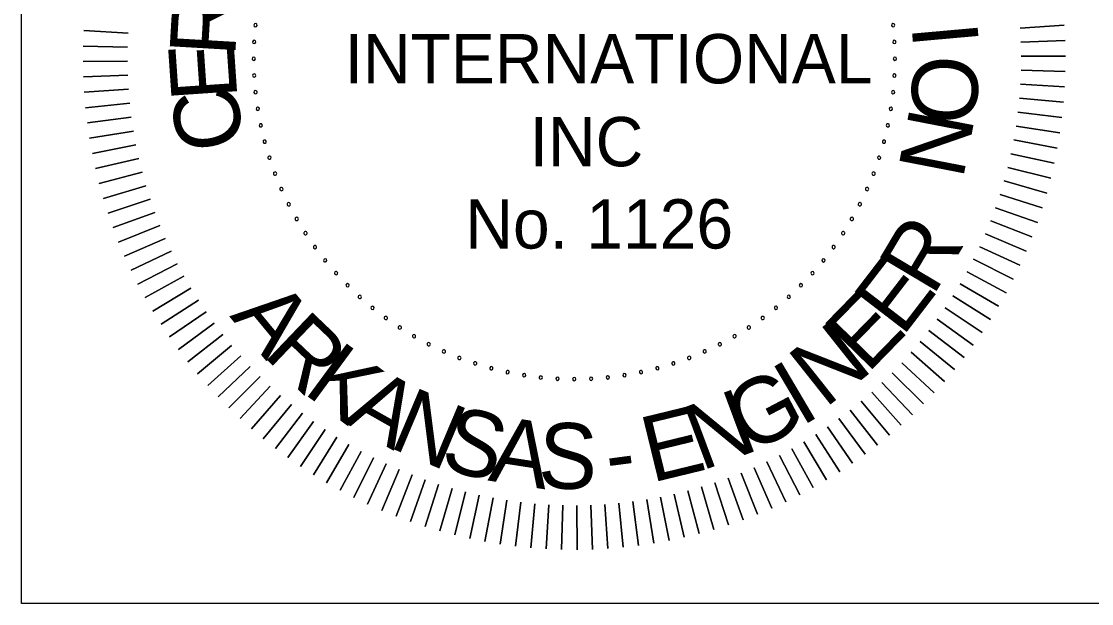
# Model space of a CAD drawing. Extents: x -984 to 3998, y 83 to 2143.
# Drawn here: x 2730.1 to 3001.2, y 212.7 to 360.3 of the extents above; entities that cross this region are included whole.
import ezdxf

# ---------------------------------------------------------------- set-up
doc = ezdxf.new("R2010")
doc.units = 0
doc.layers.add('Level 55', color=7, linetype='Continuous')
doc.layers.add('Level 57', color=7, linetype='Continuous')

msp = doc.modelspace()

# ---------------------------------------------------------------- linework, layer by layer
at = {"layer": 'Level 55'}
for points in [[(2757.15, 357.32), (2745.94, 357.97)], [(2745.94, 357.97), (2757.15, 357.32)], [(2994.33, 359.35), (2983.13, 358.58)], [(2983.13, 358.58), (2994.33, 359.35)], [(2994.54, 355.45), (2983.32, 355.03)], [(2983.32, 355.03), (2994.54, 355.45)], [(2757, 353.77), (2745.78, 354.06)], [(2745.78, 354.06), (2757, 353.77)], [(2756.96, 350.21), (2745.74, 350.15)], [(2745.74, 350.15), (2756.96, 350.21)], [(2994.62, 351.54), (2983.4, 351.48)], [(2983.4, 351.48), (2994.62, 351.54)], [(2994.58, 347.63), (2983.36, 347.92)], [(2983.36, 347.92), (2994.58, 347.63)], [(2757.04, 346.66), (2745.82, 346.24)], [(2745.82, 346.24), (2757.04, 346.66)], [(2994.42, 343.72), (2983.21, 344.37)], [(2983.21, 344.37), (2994.42, 343.72)], [(2757.23, 343.11), (2746.03, 342.34)], [(2746.03, 342.34), (2757.23, 343.11)], [(2757.53, 339.56), (2746.36, 338.44)], [(2746.36, 338.44), (2757.53, 339.56)], [(2994.13, 339.82), (2982.95, 340.82)], [(2982.95, 340.82), (2994.13, 339.82)], [(2993.73, 335.94), (2982.58, 337.28)], [(2982.58, 337.28), (2993.73, 335.94)], [(2757.94, 336.03), (2746.81, 334.56)], [(2746.81, 334.56), (2757.94, 336.03)], [(2993.2, 332.06), (2982.1, 333.76)], [(2982.1, 333.76), (2993.2, 332.06)], [(2758.46, 332.51), (2747.38, 330.69)], [(2747.38, 330.69), (2758.46, 332.51)], [(2759.09, 329.01), (2748.08, 326.85)], [(2748.08, 326.85), (2759.09, 329.01)], [(2992.55, 328.21), (2981.51, 330.25)], [(2981.51, 330.25), (2992.55, 328.21)], [(2759.83, 325.53), (2748.89, 323.02)], [(2748.89, 323.02), (2759.83, 325.53)], [(2991.77, 324.38), (2980.81, 326.76)], [(2980.81, 326.76), (2991.77, 324.38)], [(2990.88, 320.57), (2980, 323.3)], [(2980, 323.3), (2990.88, 320.57)], [(2760.68, 322.08), (2749.82, 319.23)], [(2749.82, 319.23), (2760.68, 322.08)], [(2761.64, 318.65), (2750.88, 315.46)], [(2750.88, 315.46), (2761.64, 318.65)], [(2989.87, 316.79), (2979.08, 319.86)], [(2979.08, 319.86), (2989.87, 316.79)], [(2762.7, 315.26), (2752.05, 311.73)], [(2752.05, 311.73), (2762.7, 315.26)], [(2988.74, 313.05), (2978.05, 316.46)], [(2978.05, 316.46), (2988.74, 313.05)], [(2763.87, 311.9), (2753.33, 308.04)], [(2753.33, 308.04), (2763.87, 311.9)], [(2987.5, 309.35), (2976.92, 313.09)], [(2976.92, 313.09), (2987.5, 309.35)], [(2986.14, 305.68), (2975.68, 309.75)], [(2975.68, 309.75), (2986.14, 305.68)], [(2765.15, 308.58), (2754.74, 304.39)], [(2754.74, 304.39), (2765.15, 308.58)], [(2984.66, 302.06), (2974.34, 306.46)], [(2974.34, 306.46), (2984.66, 302.06)], [(2766.53, 305.3), (2756.25, 300.79)], [(2756.25, 300.79), (2766.53, 305.3)], [(2768.01, 302.07), (2757.88, 297.23)], [(2757.88, 297.23), (2768.01, 302.07)], [(2983.07, 298.49), (2972.89, 303.21)], [(2972.89, 303.21), (2983.07, 298.49)], [(2769.59, 298.88), (2759.62, 293.73)], [(2759.62, 293.73), (2769.59, 298.88)], [(2981.37, 294.97), (2971.34, 300.01)], [(2971.34, 300.01), (2981.37, 294.97)], [(2771.27, 295.75), (2761.47, 290.29)], [(2761.47, 290.29), (2771.27, 295.75)], [(2979.56, 291.5), (2969.7, 296.86)], [(2969.7, 296.86), (2979.56, 291.5)], [(2977.64, 288.1), (2967.95, 293.76)], [(2967.95, 293.76), (2977.64, 288.1)], [(2773.05, 292.67), (2763.42, 286.9)], [(2763.42, 286.9), (2773.05, 292.67)], [(2975.62, 284.75), (2966.11, 290.71)], [(2966.11, 290.71), (2975.62, 284.75)], [(2774.93, 289.65), (2765.49, 283.58)], [(2765.49, 283.58), (2774.93, 289.65)], [(2973.49, 281.47), (2964.18, 287.73)], [(2964.18, 287.73), (2973.49, 281.47)], [(2776.9, 286.69), (2767.65, 280.33)], [(2767.65, 280.33), (2776.9, 286.69)], [(2971.26, 278.26), (2962.15, 284.81)], [(2962.15, 284.81), (2971.26, 278.26)], [(2778.96, 283.79), (2769.92, 277.14)], [(2769.92, 277.14), (2778.96, 283.79)], [(2781.11, 280.96), (2772.28, 274.03)], [(2772.28, 274.03), (2781.11, 280.96)], [(2968.93, 275.12), (2960.03, 281.95)], [(2960.03, 281.95), (2968.93, 275.12)], [(2783.35, 278.19), (2774.74, 270.99)], [(2774.74, 270.99), (2783.35, 278.19)], [(2966.51, 272.06), (2957.82, 279.16)], [(2957.82, 279.16), (2966.51, 272.06)], [(2785.67, 275.5), (2777.3, 268.03)], [(2777.3, 268.03), (2785.67, 275.5)], [(2963.98, 269.07), (2955.52, 276.45)], [(2955.52, 276.45), (2963.98, 269.07)], [(2788.08, 272.88), (2779.94, 265.16)], [(2779.94, 265.16), (2788.08, 272.88)], [(2958.66, 263.34), (2950.68, 271.23)], [(2950.68, 271.23), (2958.66, 263.34)], [(2961.37, 266.17), (2953.14, 273.8)], [(2953.14, 273.8), (2961.37, 266.17)], [(2790.57, 270.34), (2782.68, 262.36)], [(2782.68, 262.36), (2790.57, 270.34)], [(2955.87, 260.61), (2948.14, 268.75)], [(2948.14, 268.75), (2955.87, 260.61)], [(2793.14, 267.88), (2785.5, 259.66)], [(2785.5, 259.66), (2793.14, 267.88)], [(2952.99, 257.96), (2945.53, 266.34)], [(2945.53, 266.34), (2952.99, 257.96)], [(2788.41, 257.04), (2795.78, 265.5)], [(2795.78, 265.5), (2788.41, 257.04)], [(2791.39, 254.52), (2798.5, 263.21)], [(2798.5, 263.21), (2791.39, 254.52)], [(2950.04, 255.41), (2942.83, 264.01)], [(2942.83, 264.01), (2950.04, 255.41)], [(2794.46, 252.09), (2801.29, 261)], [(2801.29, 261), (2794.46, 252.09)], [(2947, 252.94), (2940.07, 261.77)], [(2940.07, 261.77), (2947, 252.94)], [(2797.6, 249.76), (2804.14, 258.88)], [(2804.14, 258.88), (2797.6, 249.76)], [(2943.89, 250.58), (2937.24, 259.62)], [(2937.24, 259.62), (2943.89, 250.58)], [(2800.81, 247.53), (2807.07, 256.85)], [(2807.07, 256.85), (2800.81, 247.53)], [(2804.09, 245.41), (2810.05, 254.92)], [(2810.05, 254.92), (2804.09, 245.41)], [(2937.44, 246.15), (2931.38, 255.59)], [(2931.38, 255.59), (2937.44, 246.15)], [(2940.7, 248.31), (2934.34, 257.56)], [(2934.34, 257.56), (2940.7, 248.31)], [(2807.43, 243.38), (2813.09, 253.07)], [(2813.09, 253.07), (2807.43, 243.38)], [(2934.12, 244.09), (2928.36, 253.72)], [(2928.36, 253.72), (2934.12, 244.09)], [(2810.84, 241.46), (2816.19, 251.33)], [(2816.19, 251.33), (2810.84, 241.46)], [(2814.3, 239.65), (2819.34, 249.68)], [(2819.34, 249.68), (2814.3, 239.65)], [(2927.29, 240.28), (2922.14, 250.25)], [(2922.14, 250.25), (2927.29, 240.28)], [(2930.74, 242.13), (2925.28, 251.94)], [(2925.28, 251.94), (2930.74, 242.13)], [(2817.82, 237.95), (2822.55, 248.13)], [(2822.55, 248.13), (2817.82, 237.95)], [(2920.24, 236.92), (2915.72, 247.19)], [(2915.72, 247.19), (2920.24, 236.92)], [(2923.79, 238.54), (2918.96, 248.67)], [(2918.96, 248.67), (2923.79, 238.54)], [(2821.4, 236.37), (2825.8, 246.69)], [(2825.8, 246.69), (2821.4, 236.37)], [(2825.02, 234.89), (2829.09, 245.35)], [(2829.09, 245.35), (2825.02, 234.89)], [(2828.68, 233.53), (2832.42, 244.11)], [(2832.42, 244.11), (2828.68, 233.53)], [(2912.99, 234), (2909.13, 244.54)], [(2909.13, 244.54), (2912.99, 234)], [(2916.63, 235.4), (2912.45, 245.81)], [(2912.45, 245.81), (2916.63, 235.4)], [(2832.39, 232.28), (2835.8, 242.97)], [(2835.8, 242.97), (2832.39, 232.28)], [(2836.13, 231.15), (2839.2, 241.95)], [(2839.2, 241.95), (2836.13, 231.15)], [(2901.8, 230.49), (2898.95, 241.34)], [(2898.95, 241.34), (2901.8, 230.49)], [(2905.56, 231.54), (2902.37, 242.3)], [(2902.37, 242.3), (2905.56, 231.54)], [(2909.29, 232.71), (2905.77, 243.36)], [(2905.77, 243.36), (2909.29, 232.71)], [(2839.91, 230.14), (2842.64, 241.03)], [(2842.64, 241.03), (2839.91, 230.14)], [(2843.71, 229.25), (2846.1, 240.22)], [(2846.1, 240.22), (2843.71, 229.25)], [(2847.54, 228.48), (2849.59, 239.52)], [(2849.59, 239.52), (2847.54, 228.48)], [(2851.4, 227.83), (2853.09, 238.92)], [(2853.09, 238.92), (2851.4, 227.83)], [(2890.33, 228.05), (2888.52, 239.12)], [(2888.52, 239.12), (2890.33, 228.05)], [(2894.18, 228.74), (2892.02, 239.75)], [(2892.02, 239.75), (2894.18, 228.74)], [(2898, 229.55), (2895.49, 240.49)], [(2895.49, 240.49), (2898, 229.55)], [(2855.27, 227.3), (2856.62, 238.44)], [(2856.62, 238.44), (2855.27, 227.3)], [(2859.16, 226.89), (2860.15, 238.07)], [(2860.15, 238.07), (2859.16, 226.89)], [(2863.06, 226.61), (2863.7, 237.81)], [(2863.7, 237.81), (2863.06, 226.61)], [(2866.97, 226.45), (2867.26, 237.66)], [(2867.26, 237.66), (2866.97, 226.45)], [(2870.87, 226.41), (2870.81, 237.63)], [(2870.81, 237.63), (2870.87, 226.41)], [(2874.78, 226.49), (2874.37, 237.7)], [(2874.37, 237.7), (2874.78, 226.49)], [(2878.69, 226.7), (2877.92, 237.89)], [(2877.92, 237.89), (2878.69, 226.7)], [(2882.58, 227.02), (2881.46, 238.19)], [(2881.46, 238.19), (2882.58, 227.02)], [(2886.47, 227.47), (2885, 238.6)], [(2885, 238.6), (2886.47, 227.47)]]:
    msp.add_lwpolyline(points, dxfattribs=at)
for centre, start, end in [((2789.41, 359.33), 84, 264), ((2789.41, 359.33), 264, 84), ((2950.95, 359.33), 96, 276), ((2950.95, 359.33), 276, 96), ((2789.08, 355.1), 87, 267), ((2789.08, 355.1), 267, 87), ((2951.28, 355.1), 93, 273), ((2951.28, 355.1), 273, 93), ((2788.97, 350.85), 90, 270), ((2788.97, 350.85), 270, 90), ((2951.4, 350.85), 90, 270), ((2951.4, 350.85), 270, 90), ((2789.08, 346.59), 93, 273), ((2789.08, 346.59), 273, 93), ((2951.28, 346.59), 87, 267), ((2951.28, 346.59), 267, 87), ((2789.41, 342.36), 96, 276), ((2789.41, 342.36), 276, 96), ((2950.95, 342.36), 84, 264), ((2950.95, 342.36), 264, 84), ((2789.97, 338.14), 99, 279), ((2789.97, 338.14), 279, 99), ((2950.4, 338.14), 81, 261), ((2950.4, 338.14), 261, 81), ((2790.74, 333.96), 102, 282), ((2790.74, 333.96), 282, 102), ((2949.62, 333.96), 78, 258), ((2949.62, 333.96), 258, 78), ((2791.73, 329.83), 105, 285), ((2791.73, 329.83), 285, 105), ((2948.63, 329.83), 75, 255), ((2948.63, 329.83), 255, 75), ((2792.94, 325.75), 108, 288), ((2792.94, 325.75), 288, 108), ((2947.42, 325.75), 72, 252), ((2947.42, 325.75), 252, 72), ((2794.36, 321.74), 111, 291), ((2794.36, 321.74), 291, 111), ((2946, 321.74), 69, 249), ((2946, 321.74), 249, 69), ((2795.99, 317.81), 114, 294), ((2795.99, 317.81), 294, 114), ((2944.37, 317.81), 66, 246), ((2944.37, 317.81), 246, 66), ((2797.82, 313.97), 117, 297), ((2797.82, 313.97), 297, 117), ((2942.54, 313.97), 63, 243), ((2942.54, 313.97), 243, 63), ((2799.85, 310.24), 120, 300), ((2799.85, 310.24), 300, 120), ((2940.52, 310.24), 60, 240), ((2940.52, 310.24), 240, 60), ((2802.07, 306.61), 123, 303), ((2802.07, 306.61), 303, 123), ((2938.29, 306.61), 57, 237), ((2938.29, 306.61), 237, 57), ((2804.48, 303.11), 126, 306), ((2804.48, 303.11), 306, 126), ((2935.89, 303.11), 54, 234), ((2935.89, 303.11), 234, 54), ((2807.07, 299.74), 129, 309), ((2807.07, 299.74), 309, 129), ((2933.3, 299.74), 51, 231), ((2933.3, 299.74), 231, 51), ((2809.83, 296.5), 132, 312), ((2809.83, 296.5), 312, 132), ((2930.54, 296.5), 48, 228), ((2930.54, 296.5), 228, 48), ((2812.75, 293.42), 135, 315), ((2812.75, 293.42), 315, 135), ((2927.61, 293.42), 45, 225), ((2927.61, 293.42), 225, 45), ((2815.84, 290.49), 138, 318), ((2815.84, 290.49), 318, 138), ((2924.52, 290.49), 42, 222), ((2924.52, 290.49), 222, 42), ((2819.07, 287.73), 141, 321), ((2819.07, 287.73), 321, 141), ((2921.29, 287.73), 39, 219), ((2921.29, 287.73), 219, 39), ((2822.44, 285.14), 144, 324), ((2822.44, 285.14), 324, 144), ((2917.92, 285.14), 36, 216), ((2917.92, 285.14), 216, 36), ((2825.95, 282.73), 147, 327), ((2825.95, 282.73), 327, 147), ((2914.41, 282.73), 33, 213), ((2914.41, 282.73), 213, 33), ((2829.57, 280.51), 150, 330), ((2829.57, 280.51), 330, 150), ((2910.79, 280.51), 30, 210), ((2910.79, 280.51), 210, 30), ((2833.31, 278.48), 153, 333), ((2833.31, 278.48), 333, 153), ((2837.15, 276.65), 156, 336), ((2837.15, 276.65), 336, 156), ((2903.21, 276.65), 24, 204), ((2903.21, 276.65), 204, 24), ((2907.05, 278.48), 27, 207), ((2907.05, 278.48), 207, 27), ((2841.08, 275.02), 159, 339), ((2841.08, 275.02), 339, 159), ((2845.08, 273.61), 342, 162), ((2895.28, 273.61), 18, 198), ((2899.29, 275.02), 21, 201), ((2899.29, 275.02), 201, 21), ((2845.08, 273.61), 162, 342), ((2849.16, 272.4), 165, 345), ((2849.16, 272.4), 345, 165), ((2853.3, 271.41), 168, 348), ((2853.3, 271.41), 348, 168), ((2887.07, 271.41), 12, 192), ((2887.07, 271.41), 192, 12), ((2891.2, 272.4), 15, 195), ((2891.2, 272.4), 195, 15), ((2895.28, 273.61), 198, 18), ((2857.48, 270.63), 351, 171), ((2857.48, 270.63), 171, 351), ((2861.69, 270.08), 354, 174), ((2861.69, 270.08), 174, 354), ((2865.93, 269.74), 357, 177), ((2865.93, 269.74), 177, 357), ((2870.18, 269.63), 0, 180), ((2870.18, 269.63), 180, 0), ((2874.43, 269.74), 3, 183), ((2874.43, 269.74), 183, 3), ((2878.67, 270.08), 6, 186), ((2878.67, 270.08), 186, 6), ((2882.89, 270.63), 9, 189), ((2882.89, 270.63), 189, 9)]:
    msp.add_arc(centre, 0.417, start, end, dxfattribs=at)
at = {"layer": 'Level 57'}
msp.add_lwpolyline([(2730.1, 488.67), (3010.37, 488.67), (3010.37, 212.74), (2730.1, 212.74)], close=True, dxfattribs=at)

# ---------------------------------------------------------------- texts
at = {"layer": 'Level 55'}
for s, rotation, p in [('R', 86.6268, (2784.23, 351.21)), ('I', 275.1216, (2955.59, 359.26)), ('E', 93.9203, (2784.85, 340.8)), ('O', 267.0743, (2956.18, 352.09)), ('C', 101.2137, (2786.98, 329.21)), ('N', 259.0269, (2955.3, 338.99)), ('R', 59.2262, (2961.05, 290.4)), ('E', 52.4765, (2953.31, 280.14)), ('A', 309.5859, (2782.72, 285.58)), ('E', 45.7268, (2944.43, 270.86)), ('R', 316.3356, (2790.99, 275.75)), ('N', 38.4196, (2933.65, 262.07)), ('K', 323.6428, (2801.19, 266.29)), ('I', 30.5495, (2927.6, 257.48)), ('A', 330.3925, (2811.6, 258.77)), ('G', 27.7404, (2914.42, 250.48)), ('N', 337.1422, (2822.83, 252.52)), ('N', 20.4332, (2902.29, 246.28)), ('S', 344.4494, (2835.72, 247.3)), ('E', 13.6835, (2889.73, 243.34)), ('A', 351.1991, (2848.13, 243.96)), ('S', 357.9489, (2860.85, 242.11)), ('-', 7.5077, (2879.03, 242.07))]:
    msp.add_text(s, height=16.67, rotation=rotation, dxfattribs=at).set_placement(p)
for s, height, p in [(' INTERNATIONAL', 12.5016, (2807.34, 344.6)), ('INC', 12.502, (2858.86, 323.58)), (' No. 1126', 12.502, (2837.92, 302.74))]:
    msp.add_text(s, height=height, dxfattribs=at).set_placement(p)

doc.saveas('drawing.dxf')
